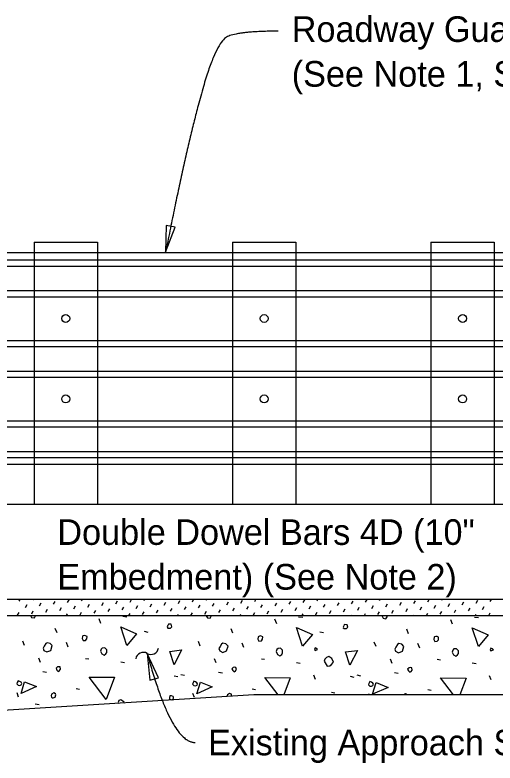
# Model space of a CAD drawing. Extents: x 21526.6 to 21595.9, y 56114.9 to 56157.2.
# Drawn here: x 21557.64 to 21561.42, y 56133.17 to 56139.06 of the extents above; entities that cross this region are included whole.
import ezdxf

# ---------------------------------------------------------------- set-up
doc = ezdxf.new("R2010")
doc.units = 0
for name, color, linetype in [('AdhocPoint_dp', 7, 'Continuous'), ('Border', 7, 'Continuous'), ('Patterning', 7, 'Continuous'), ('PlotBorder_dp', 7, 'Continuous'), ('SheetBorder_dp', 7, 'Continuous')]:
    doc.layers.add(name, color=color, linetype=linetype)

msp = doc.modelspace()

# ---------------------------------------------------------------- linework, layer by layer
at = {"layer": 'AdhocPoint_dp'}
for p, q in [((21554.3018, 56135.21), (21562.4118, 56135.21)), ((21565.8764, 56134.4601), (21554.3018, 56134.4601)), ((21554.3018, 56134.3351), (21565.8764, 56134.3351)), ((21559.5217, 56133.71), (21555.5217, 56133.46)), ((21565.8764, 56133.71), (21559.5217, 56133.71))]:
    msp.add_line(p, q, dxfattribs=at)
at = {"layer": 'Patterning'}
for p, q in [((21557.7913, 56137.2725), (21557.7913, 56135.21)), ((21557.7913, 56137.2725), (21558.2913, 56137.2725)), ((21558.2913, 56137.2725), (21558.2913, 56135.21)), ((21559.3538, 56137.2725), (21559.3538, 56135.21)), ((21559.3538, 56137.2725), (21559.8538, 56137.2725)), ((21559.8538, 56137.2725), (21559.8538, 56135.21)), ((21560.9163, 56137.2725), (21560.9163, 56135.21)), ((21560.9163, 56137.2725), (21561.4163, 56137.2725)), ((21561.4163, 56137.2725), (21561.4163, 56135.21)), ((21552.8484, 56137.1336), (21564.1633, 56137.1336)), ((21552.8484, 56137.0853), (21564.1633, 56137.0853)), ((21552.8484, 56136.8925), (21564.1633, 56136.8925)), ((21552.8484, 56136.8443), (21564.1633, 56136.8443)), ((21552.8484, 56136.5003), (21564.1633, 56136.5003)), ((21552.8484, 56136.4521), (21564.1633, 56136.4521)), ((21552.8484, 56136.2593), (21564.1633, 56136.2593)), ((21552.8484, 56136.2112), (21564.1633, 56136.2112)), ((21552.8484, 56135.8672), (21564.1633, 56135.8672)), ((21552.8484, 56135.819), (21564.1633, 56135.819)), ((21552.8484, 56135.6262), (21564.1633, 56135.6262)), ((21552.8484, 56135.5779), (21564.1633, 56135.5779)), ((21557.6751, 56134.447), (21557.6827, 56134.4601)), ((21557.7857, 56134.4599), (21557.7858, 56134.4601)), ((21557.9452, 56134.424), (21557.9581, 56134.4464)), ((21558.0558, 56134.437), (21558.0688, 56134.4594)), ((21558.1664, 56134.45), (21558.1723, 56134.4601)), ((21558.4365, 56134.4271), (21558.4495, 56134.4495)), ((21558.5472, 56134.44), (21558.5588, 56134.4601)), ((21558.6578, 56134.453), (21558.6619, 56134.4601)), ((21558.9279, 56134.4301), (21558.9409, 56134.4525)), ((21559.0385, 56134.4431), (21559.0484, 56134.4601)), ((21559.1492, 56134.456), (21559.1515, 56134.4601)), ((21559.3086, 56134.4201), (21559.3216, 56134.4425)), ((21559.4193, 56134.4331), (21559.4322, 56134.4555)), ((21559.5299, 56134.4461), (21559.538, 56134.4601)), ((21559.6405, 56134.459), (21559.6412, 56134.4601)), ((21559.8, 56134.4232), (21559.813, 56134.4456)), ((21559.9106, 56134.4361), (21559.9236, 56134.4585)), ((21560.0213, 56134.4491), (21560.0276, 56134.4601)), ((21560.2914, 56134.4262), (21560.3043, 56134.4486)), ((21560.402, 56134.4391), (21560.4141, 56134.4601)), ((21560.5126, 56134.4521), (21560.5173, 56134.4601)), ((21560.7827, 56134.4292), (21560.7957, 56134.4516)), ((21560.8934, 56134.4422), (21560.9038, 56134.4601)), ((21561.004, 56134.4551), (21561.0069, 56134.4601)), ((21561.2741, 56134.4322), (21561.2871, 56134.4546)), ((21561.3847, 56134.4452), (21561.3934, 56134.4601)), ((21557.7239, 56134.3981), (21557.7369, 56134.4205)), ((21557.8345, 56134.4111), (21557.8475, 56134.4335)), ((21557.8834, 56134.3623), (21557.8963, 56134.3846)), ((21557.994, 56134.3752), (21558.007, 56134.3976)), ((21558.1046, 56134.3882), (21558.1176, 56134.4106)), ((21558.2153, 56134.4011), (21558.2282, 56134.4235)), ((21558.3259, 56134.4141), (21558.3389, 56134.4365)), ((21558.3747, 56134.3653), (21558.3877, 56134.3877)), ((21558.4854, 56134.3782), (21558.4983, 56134.4006)), ((21558.596, 56134.3912), (21558.609, 56134.4136)), ((21558.7066, 56134.4042), (21558.7196, 56134.4266)), ((21558.8173, 56134.4171), (21558.8302, 56134.4395)), ((21558.8661, 56134.3683), (21558.8791, 56134.3907)), ((21558.9767, 56134.3813), (21558.9897, 56134.4036)), ((21559.0874, 56134.3942), (21559.1003, 56134.4166)), ((21559.198, 56134.4072), (21559.211, 56134.4296)), ((21559.3575, 56134.3713), (21559.3704, 56134.3937)), ((21559.4681, 56134.3843), (21559.4811, 56134.4067)), ((21559.5787, 56134.3972), (21559.5917, 56134.4196)), ((21559.6894, 56134.4102), (21559.7023, 56134.4326)), ((21559.7382, 56134.3614), (21559.7512, 56134.3838)), ((21559.8488, 56134.3743), (21559.8618, 56134.3967)), ((21559.9595, 56134.3873), (21559.9724, 56134.4097)), ((21560.0701, 56134.4003), (21560.0831, 56134.4226)), ((21560.1807, 56134.4132), (21560.1937, 56134.4356)), ((21560.2296, 56134.3644), (21560.2425, 56134.3868)), ((21560.3402, 56134.3774), (21560.3532, 56134.3997)), ((21560.4508, 56134.3903), (21560.4638, 56134.4127)), ((21560.5615, 56134.4033), (21560.5744, 56134.4257)), ((21560.6721, 56134.4162), (21560.6851, 56134.4386)), ((21560.7209, 56134.3674), (21560.7339, 56134.3898)), ((21560.8316, 56134.3804), (21560.8445, 56134.4028)), ((21560.9422, 56134.3933), (21560.9552, 56134.4157)), ((21561.0528, 56134.4063), (21561.0658, 56134.4287)), ((21561.1635, 56134.4193), (21561.1764, 56134.4417)), ((21561.2123, 56134.3704), (21561.2253, 56134.3928)), ((21561.3229, 56134.3834), (21561.3359, 56134.4058)), ((21557.6621, 56134.3363), (21557.6751, 56134.3587)), ((21557.7727, 56134.3493), (21557.7857, 56134.3717)), ((21557.9447, 56134.3351), (21557.9452, 56134.3358)), ((21558.0479, 56134.3351), (21558.0558, 56134.3488)), ((21558.1535, 56134.3393), (21558.1664, 56134.3617)), ((21558.2641, 56134.3523), (21558.2771, 56134.3747)), ((21558.4343, 56134.3351), (21558.4365, 56134.3388)), ((21558.4907, 56134.3291), (21558.5225, 56134.3256)), ((21558.5375, 56134.3351), (21558.5472, 56134.3518)), ((21558.6448, 56134.3424), (21558.6578, 56134.3648)), ((21558.7555, 56134.3553), (21558.7684, 56134.3777)), ((21558.924, 56134.3351), (21558.9279, 56134.3418)), ((21559.0271, 56134.3351), (21559.0385, 56134.3548)), ((21559.1362, 56134.3454), (21559.1492, 56134.3678)), ((21559.2468, 56134.3583), (21559.2598, 56134.3807)), ((21559.4136, 56134.3351), (21559.4193, 56134.3449)), ((21559.5169, 56134.3354), (21559.5299, 56134.3578)), ((21559.6276, 56134.3484), (21559.6405, 56134.3708)), ((21559.8754, 56134.3256), (21559.9072, 56134.322)), ((21559.9032, 56134.3351), (21559.9106, 56134.3479)), ((21560.0083, 56134.3385), (21560.0213, 56134.3609)), ((21560.1189, 56134.3514), (21560.1319, 56134.3738)), ((21560.2897, 56134.3351), (21560.2914, 56134.3379)), ((21560.3928, 56134.3351), (21560.402, 56134.3509)), ((21560.4997, 56134.3415), (21560.5126, 56134.3639)), ((21560.6103, 56134.3544), (21560.6233, 56134.3768)), ((21560.7793, 56134.3351), (21560.7827, 56134.341)), ((21560.8824, 56134.3351), (21560.8934, 56134.3539)), ((21560.991, 56134.3445), (21561.004, 56134.3669)), ((21561.1017, 56134.3575), (21561.1146, 56134.3799)), ((21561.2689, 56134.3351), (21561.2741, 56134.344)), ((21561.3721, 56134.3351), (21561.3847, 56134.3569)), ((21558.3181, 56134.2732), (21558.304, 56134.3085)), ((21559.7028, 56134.2696), (21559.6886, 56134.305)), ((21561.0875, 56134.2661), (21561.0733, 56134.3014)), ((21561.2601, 56134.322), (21561.2919, 56134.3185)), ((21557.9723, 56134.1983), (21557.9581, 56134.2336)), ((21558.6587, 56134.2107), (21558.6869, 56134.2036)), ((21559.3569, 56134.1947), (21559.3428, 56134.2301)), ((21560.0433, 56134.2071), (21560.0716, 56134.2001)), ((21560.7416, 56134.1912), (21560.7275, 56134.2266)), ((21557.7159, 56134.0975), (21557.7018, 56134.1329)), ((21558.06, 56134.0858), (21558.0459, 56134.1211)), ((21559.1006, 56134.094), (21559.0865, 56134.1293)), ((21559.4447, 56134.0822), (21559.4306, 56134.1176)), ((21560.4853, 56134.0904), (21560.4711, 56134.1258)), ((21560.8294, 56134.0787), (21560.8152, 56134.1141)), ((21557.8414, 56133.9649), (21557.8291, 56133.9985)), ((21558.1979, 56133.9974), (21558.2227, 56133.9938)), ((21559.2261, 56133.9614), (21559.2137, 56133.995)), ((21559.5826, 56133.9938), (21559.6073, 56133.9903)), ((21560.6108, 56133.9579), (21560.5984, 56133.9915)), ((21560.9673, 56133.9903), (21560.992, 56133.9868)), ((21558.4737, 56133.9691), (21558.5037, 56133.9638)), ((21559.8584, 56133.9656), (21559.8884, 56133.9603)), ((21561.243, 56133.962), (21561.2731, 56133.9567)), ((21557.8603, 56133.8931), (21557.8903, 56133.8878)), ((21558.8962, 56133.8613), (21558.9245, 56133.8542)), ((21558.9486, 56133.8712), (21558.9769, 56133.8642)), ((21559.2449, 56133.8895), (21559.275, 56133.8842)), ((21560.0068, 56133.8312), (21559.9945, 56133.8648)), ((21560.2808, 56133.8577), (21560.3091, 56133.8507)), ((21560.3333, 56133.8677), (21560.3615, 56133.8606)), ((21560.6296, 56133.886), (21560.6597, 56133.8807)), ((21561.3915, 56133.8277), (21561.3791, 56133.8613)), ((21558.1237, 56133.7605), (21558.1502, 56133.7552)), ((21559.5083, 56133.757), (21559.5349, 56133.7517)), ((21560.893, 56133.7534), (21560.9195, 56133.7481)), ((21557.67, 56133.6922), (21557.6576, 56133.7258)), ((21559.0546, 56133.6887), (21559.0423, 56133.7222)), ((21560.1341, 56133.7322), (21560.1606, 56133.7269)), ((21560.4301, 56133.71), (21560.4269, 56133.7187)), ((21557.8002, 56133.6385), (21557.832, 56133.635))]:
    msp.add_line(p, q, dxfattribs=at)
for points in [[(21557.7643, 56134.3351), (21557.7725, 56134.3203), (21557.7937, 56134.3167), (21557.8026, 56134.3326), (21557.8032, 56134.3351)], [(21559.1471, 56134.3351), (21559.1483, 56134.3326)], [(21559.1483, 56134.3326), (21559.1572, 56134.3167), (21559.1784, 56134.3132), (21559.1872, 56134.3291), (21559.1887, 56134.3351)], [(21560.53, 56134.3351), (21560.533, 56134.3291)], [(21560.533, 56134.3291), (21560.5419, 56134.3132), (21560.5631, 56134.3097), (21560.5719, 56134.3256), (21560.5743, 56134.3351)], [(21558.846, 56134.2354), (21558.8673, 56134.2354), (21558.8779, 56134.246), (21558.8726, 56134.2655), (21558.8496, 56134.2672), (21558.846, 56134.2566), (21558.8407, 56134.2478), (21558.846, 56134.2354), (21558.8425, 56134.2389)], [(21558.5214, 56134.0981), (21558.4737, 56134.2449), (21558.5992, 56134.1901), (21558.5214, 56134.0981)], [(21559.9061, 56134.0946), (21559.8584, 56134.2413), (21559.9839, 56134.1865), (21559.9061, 56134.0946)], [(21560.2307, 56134.2319), (21560.2519, 56134.2319), (21560.2625, 56134.2425), (21560.2572, 56134.2619), (21560.2343, 56134.2637), (21560.2307, 56134.2531), (21560.2254, 56134.2442), (21560.2307, 56134.2319), (21560.2272, 56134.2354)], [(21561.2908, 56134.0911), (21561.243, 56134.2378), (21561.3685, 56134.183), (21561.2908, 56134.0911)], [(21558.1696, 56134.1529), (21558.1785, 56134.137), (21558.1979, 56134.1388), (21558.2067, 56134.1512), (21558.2085, 56134.1706), (21558.1961, 56134.1759), (21558.1873, 56134.1777), (21558.1767, 56134.1742), (21558.1732, 56134.1706), (21558.1696, 56134.1529)], [(21559.5543, 56134.1494), (21559.5631, 56134.1335), (21559.5826, 56134.1353), (21559.5914, 56134.1476), (21559.5932, 56134.1671), (21559.5808, 56134.1724), (21559.572, 56134.1742), (21559.5614, 56134.1706), (21559.5578, 56134.1671), (21559.5543, 56134.1494)], [(21560.939, 56134.1459), (21560.9478, 56134.13), (21560.9673, 56134.1317), (21560.9761, 56134.1441), (21560.9779, 56134.1636), (21560.9655, 56134.1689), (21560.9567, 56134.1706), (21560.946, 56134.1671), (21560.9425, 56134.1636), (21560.939, 56134.1459)], [(21557.8697, 56134.0604), (21557.8927, 56134.048), (21557.9228, 56134.0604), (21557.9351, 56134.0975), (21557.9175, 56134.1152), (21557.8945, 56134.1205), (21557.8839, 56134.1134), (21557.8715, 56134.094), (21557.8627, 56134.0781), (21557.8697, 56134.0604)], [(21559.2544, 56134.0569), (21559.2774, 56134.0445), (21559.3074, 56134.0569), (21559.3198, 56134.094), (21559.3021, 56134.1117), (21559.2792, 56134.117), (21559.2685, 56134.1099), (21559.2562, 56134.0904), (21559.2473, 56134.0745), (21559.2544, 56134.0569)], [(21560.6391, 56134.0533), (21560.6621, 56134.041), (21560.6921, 56134.0533), (21560.7045, 56134.0904), (21560.6868, 56134.1081), (21560.6638, 56134.1134), (21560.6532, 56134.1064), (21560.6408, 56134.0869), (21560.632, 56134.071), (21560.6391, 56134.0533)], [(21558.3146, 56134.054), (21558.3252, 56134.0327), (21558.3429, 56134.0221), (21558.357, 56134.0327), (21558.3641, 56134.0433), (21558.3641, 56134.0646), (21558.3482, 56134.0805), (21558.3287, 56134.0787), (21558.3199, 56134.0699), (21558.3146, 56134.054)], [(21558.8938, 56133.9473), (21558.8602, 56134.0516), (21558.9539, 56134.0639), (21558.8938, 56133.9473)], [(21559.6993, 56134.0504), (21559.7099, 56134.0292), (21559.7275, 56134.0186), (21559.7417, 56134.0292), (21559.7488, 56134.0398), (21559.7488, 56134.061), (21559.7328, 56134.0769), (21559.7134, 56134.0752), (21559.7046, 56134.0663), (21559.6993, 56134.0504)], [(21560.0051, 56134.0593), (21560.0245, 56134.0681), (21560.0175, 56134.0752), (21560.0051, 56134.0805), (21559.9998, 56134.0681), (21560.0051, 56134.0593)], [(21560.2785, 56133.9437), (21560.2449, 56134.048), (21560.3386, 56134.0604), (21560.2785, 56133.9437)], [(21561.0839, 56134.0469), (21561.0945, 56134.0257), (21561.1122, 56134.0151), (21561.1264, 56134.0257), (21561.1334, 56134.0363), (21561.1334, 56134.0575), (21561.1175, 56134.0734), (21561.0981, 56134.0716), (21561.0892, 56134.0628), (21561.0839, 56134.0469)], [(21561.3898, 56134.0557), (21561.4092, 56134.0646), (21561.4021, 56134.0716), (21561.3898, 56134.0769), (21561.3845, 56134.0646), (21561.3898, 56134.0557)], [(21560.0758, 56133.9744), (21560.0988, 56133.9373), (21560.1218, 56133.939), (21560.1306, 56133.9479), (21560.15, 56133.9673), (21560.1377, 56133.9974), (21560.1129, 56134.0115), (21560.0952, 56134.0045), (21560.0811, 56133.9903), (21560.0758, 56133.9744)], [(21557.9716, 56133.9055), (21557.9822, 56133.8949), (21557.9928, 56133.9019), (21557.9999, 56133.9125), (21557.9964, 56133.9302), (21557.9875, 56133.932), (21557.9752, 56133.9302), (21557.9646, 56133.9196), (21557.9716, 56133.9055)], [(21559.3563, 56133.9019), (21559.3669, 56133.8913), (21559.3775, 56133.8984), (21559.3846, 56133.909), (21559.3811, 56133.9267), (21559.3722, 56133.9284), (21559.3598, 56133.9267), (21559.3492, 56133.9161), (21559.3563, 56133.9019)], [(21560.741, 56133.8984), (21560.7516, 56133.8878), (21560.7622, 56133.8949), (21560.7693, 56133.9055), (21560.7657, 56133.9231), (21560.7569, 56133.9249), (21560.7445, 56133.9231), (21560.7339, 56133.9125), (21560.741, 56133.8984)], [(21557.6664, 56133.7864), (21557.6788, 56133.7846), (21557.6912, 56133.7899), (21557.6947, 56133.8005), (21557.6894, 56133.8094), (21557.6788, 56133.8164), (21557.6664, 56133.8217), (21557.6594, 56133.8076), (21557.6558, 56133.797), (21557.6664, 56133.7864)], [(21557.6888, 56133.7216), (21557.7171, 56133.8135), (21557.8108, 56133.7764), (21557.6888, 56133.7216)], [(21558.3588, 56133.6739), (21558.2244, 56133.8507), (21558.4242, 56133.8489), (21558.3588, 56133.6739)], [(21559.0511, 56133.7829), (21559.0635, 56133.7811), (21559.0759, 56133.7864), (21559.0794, 56133.797), (21559.0741, 56133.8058), (21559.0635, 56133.8129), (21559.0511, 56133.8182), (21559.044, 56133.8041), (21559.0405, 56133.7935), (21559.0511, 56133.7829)], [(21559.0735, 56133.7181), (21559.1017, 56133.81), (21559.1954, 56133.7729), (21559.0735, 56133.7181)], [(21559.7133, 56133.71), (21559.6091, 56133.8471), (21559.8089, 56133.8454), (21559.7583, 56133.71)], [(21560.4358, 56133.7793), (21560.4482, 56133.7776), (21560.4605, 56133.7829), (21560.4641, 56133.7935), (21560.4588, 56133.8023), (21560.4482, 56133.8094), (21560.4358, 56133.8147), (21560.4287, 56133.8005), (21560.4252, 56133.7899), (21560.4358, 56133.7793)], [(21560.4581, 56133.7145), (21560.4864, 56133.8065), (21560.5801, 56133.7693), (21560.4581, 56133.7145)], [(21561.0953, 56133.71), (21560.9938, 56133.8436), (21561.1935, 56133.8418), (21561.1443, 56133.71)], [(21557.9363, 56133.6863), (21557.9433, 56133.6863), (21557.9575, 56133.6933), (21557.9628, 56133.7092), (21557.961, 56133.7181), (21557.9469, 56133.7251), (21557.9292, 56133.7145), (21557.9257, 56133.7039), (21557.9292, 56133.6933), (21557.9363, 56133.6863)], [(21558.8573, 56133.6774), (21558.8767, 56133.6721), (21558.8891, 56133.681), (21558.8909, 56133.6933), (21558.8873, 56133.6969), (21558.8732, 56133.7039), (21558.8608, 56133.7022), (21558.859, 56133.6898), (21558.8573, 56133.6774)], [(21559.3452, 56133.699), (21559.3475, 56133.7057), (21559.3457, 56133.7145), (21559.3316, 56133.7216), (21559.3139, 56133.711), (21559.3103, 56133.7004), (21559.3115, 56133.6969)], [(21560.7306, 56133.71), (21560.7304, 56133.711), (21560.7162, 56133.7181), (21560.7028, 56133.71)], [(21558.4985, 56133.6461), (21558.5002, 56133.6527), (21558.4914, 56133.6615), (21558.4754, 56133.6703), (21558.4595, 56133.665), (21558.4542, 56133.6491), (21558.4571, 56133.6435)]]:
    msp.add_lwpolyline(points, dxfattribs=at)
at = {"layer": 'PlotBorder_dp'}
for points in [[(21558.8278, 56137.1938), (21558.9023, 56137.3915), (21558.833, 56137.405)], [(21558.6823, 56134.0371), (21558.7024, 56133.8269), (21558.7706, 56133.8452)]]:
    msp.add_lwpolyline(points, close=True, dxfattribs=at)
for centre, start, end in [((21558.6515, 56133.9854), 59.26505, 170.99227), ((21558.7125, 56134.0879), 239.26505, 350.99227)]:
    msp.add_arc(centre, 0.0596, start, end, dxfattribs=at)
for points in [[(21559.7152, 56138.9342), (21559.4136, 56138.9342), (21559.2155, 56138.8481), (21558.9656, 56137.9003), (21558.8278, 56137.1938)], [(21558.6827, 56134.0369), (21558.8719, 56133.3352), (21559.061, 56133.3352)]]:
    msp.add_open_spline(points, degree=2, dxfattribs=at)
at = {"layer": 'SheetBorder_dp'}
for p, q in [((21564.1633, 56137.1891), (21552.8484, 56137.1891)), ((21564.1633, 56135.5224), (21552.8484, 56135.5224))]:
    msp.add_line(p, q, dxfattribs=at)
for centre in [(21558.0413, 56136.6724), (21559.6038, 56136.6724), (21561.1663, 56136.6724), (21558.0413, 56136.0393), (21559.6038, 56136.0393), (21561.1663, 56136.0393)]:
    msp.add_circle(centre, 0.0312, dxfattribs=at)

# ---------------------------------------------------------------- texts
at = {"layer": 'Border'}
msp.add_text('Existing Approach Slab', height=0.2016, dxfattribs=at).set_placement((21559.1619, 56133.2344))
at = {"layer": 'PlotBorder_dp'}
for s, p in [('Roadway Guardrail Transition', (21559.8207, 56138.8494)), ('(See Note 1, Sheet 1)', (21559.8207, 56138.4974)), ('Double Dowel Bars 4D (10"', (21557.9746, 56134.8907)), ('Embedment) (See Note 2)', (21557.9746, 56134.5387))]:
    msp.add_text(s, height=0.2016, dxfattribs=at).set_placement(p)

doc.saveas('drawing.dxf')
